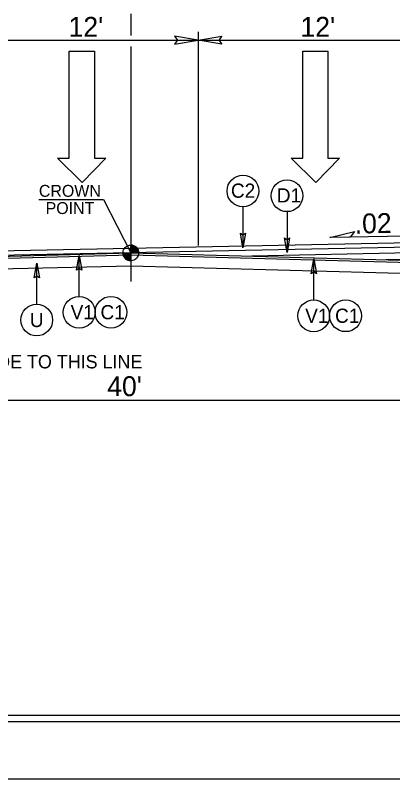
# Model space of a CAD drawing. Extents: x 957297 to 961629, y 830661 to 840840.
# Drawn here: x 959261.2 to 959409.2, y 838515.4 to 838815 of the extents above; entities that cross this region are included whole.
import ezdxf

# ---------------------------------------------------------------- set-up
doc = ezdxf.new("R2010")
doc.units = 0
for name, color, linetype in [('Default', 7, 'Continuous'), ('Old_Level_1', 7, 'Continuous'), ('Old_Level_11', 7, 'Continuous'), ('Prop CMT Pvmt Milling', 7, 'Continuous'), ('Prop Dimension Text', 7, 'Continuous'), ('Prop Lane Arrow CELL', 7, 'Continuous'), ('Sheet Plot Border Inside CELL', 7, 'Continuous'), ('Sheet Plot Border Outside CELL', 7, 'Continuous'), ('Sheet Typical CELL', 7, 'Continuous'), ('Typical ID Circle CELL', 7, 'Continuous'), ('Typical Terminator CELL', 7, 'Continuous'), ('Typical Text Grade Point CELL', 7, 'Continuous'), ('Typical Text ID Circle CELL', 7, 'Continuous')]:
    doc.layers.add(name, color=color, linetype=linetype)

# ---------------------------------------------------------------- blocks, each defined once
blk = doc.blocks.new('Lane Arrow Through')
at = {"layer": 'Prop Lane Arrow CELL'}
for p, q in [((-3.15, 1.6), (-3.15, 3.1)), ((-3.15, 3.1), (0, 0)), ((-17.15, 1.6), (-3.15, 1.6)), ((-17.15, -1.7), (-17.15, 1.6)), ((0, 0), (-3.15, -3.2)), ((-3.15, -1.7), (-17.15, -1.7)), ((-3.15, -3.2), (-3.15, -1.7))]:
    blk.add_line(p, q, dxfattribs=at)

msp = doc.modelspace()

# ---------------------------------------------------------------- linework, layer by layer
at = {"layer": 'Default'}
for p, q in [((959306.49, 838815.61), (959306.49, 838807.02)), ((959306.49, 838802.72), (959306.49, 838710.55))]:
    msp.add_line(p, q, dxfattribs=at)
at = {"layer": 'Old_Level_1'}
for p, q in [((959332.9, 838808.54), (959332.9, 838724.63)), ((959239.42, 838805.18), (959332.9, 838805.18)), ((959332.9, 838805.18), (959426.38, 838805.18)), ((959414.71, 838728.33), (959384.5, 838727.72)), ((959494.54, 838727.27), (959206.42, 838721.44)), ((959494.54, 838725.54), (959206.42, 838719.71)), ((959306.49, 838721.74), (959306.49, 838724.81)), ((959494.54, 838723.29), (959354.01, 838720.44)), ((959303.43, 838721.74), (959306.49, 838721.74)), ((959309.55, 838721.74), (959306.49, 838721.74)), ((959306.49, 838718.69), (959306.49, 838721.74)), ((959306.49, 838721.74), (959306.49, 838718.69)), ((959494.54, 838720.79), (959406.57, 838719.01)), ((959133.56, 838663.97), (959479.39, 838663.97))]:
    msp.add_line(p, q, dxfattribs=at)
for points in [[(959306.52, 838724.81), (959306.52, 838724.81), (959306.52, 838721.74)], [(959306.58, 838724.81), (959306.58, 838721.74)], [(959306.64, 838724.8), (959306.64, 838721.74)], [(959306.71, 838724.79), (959306.71, 838721.74)], [(959306.77, 838724.79), (959306.77, 838721.74)], [(959306.83, 838724.79), (959306.83, 838721.74)], [(959306.89, 838724.78), (959306.89, 838721.74)], [(959306.95, 838724.78), (959306.95, 838721.74)], [(959307, 838724.75), (959307, 838721.74)], [(959307.06, 838724.75), (959307.06, 838721.74)], [(959307.13, 838724.74), (959307.13, 838721.74)], [(959307.19, 838724.72), (959307.19, 838721.74)], [(959307.25, 838724.7), (959307.25, 838721.74)], [(959307.31, 838724.69), (959307.31, 838721.74)], [(959307.38, 838724.67), (959307.38, 838721.74)], [(959307.44, 838724.65), (959307.44, 838721.74)], [(959307.5, 838724.63), (959307.5, 838721.74)], [(959307.56, 838724.61), (959307.56, 838721.74)], [(959307.62, 838724.59), (959307.62, 838721.74)], [(959307.69, 838724.56), (959307.69, 838721.74)], [(959307.75, 838724.54), (959307.75, 838721.74)], [(959307.81, 838724.5), (959307.81, 838721.74)], [(959307.86, 838724.48), (959307.86, 838721.74)], [(959307.92, 838724.46), (959307.92, 838721.74)], [(959307.98, 838724.42), (959307.98, 838721.74)], [(959308.05, 838724.38), (959308.05, 838721.74)], [(959308.11, 838724.34), (959308.11, 838721.74)], [(959308.17, 838724.3), (959308.17, 838721.74)], [(959308.23, 838724.25), (959308.23, 838721.74)], [(959308.29, 838724.22), (959308.29, 838721.74)], [(959308.35, 838724.17), (959308.35, 838721.74)], [(959308.42, 838724.12), (959308.42, 838721.74)], [(959308.48, 838724.08), (959308.48, 838721.74)], [(959308.54, 838724.02), (959308.54, 838721.74)], [(959308.6, 838723.96), (959308.6, 838721.74)], [(959308.67, 838723.9), (959308.67, 838721.74)], [(959308.72, 838723.83), (959308.72, 838721.74)], [(959308.78, 838723.77), (959308.78, 838721.74)], [(959308.84, 838723.71), (959308.84, 838721.74)], [(959308.9, 838723.61), (959308.9, 838721.74)], [(959308.97, 838723.54), (959308.97, 838721.74)], [(959309.03, 838723.45), (959309.03, 838721.74)], [(959309.09, 838723.36), (959309.09, 838721.74)], [(959309.14, 838723.26), (959309.14, 838721.74)], [(959309.21, 838723.15), (959309.21, 838721.74)], [(959309.27, 838723.01), (959309.27, 838721.74)], [(959309.33, 838722.86), (959309.33, 838721.74)], [(959309.39, 838722.7), (959309.39, 838721.74)], [(959309.46, 838722.49), (959309.46, 838721.74)], [(959309.52, 838722.19), (959309.52, 838721.74)], [(959303.45, 838721.74), (959303.45, 838721.42)], [(959303.51, 838721.74), (959303.51, 838721.05)], [(959303.57, 838721.74), (959303.57, 838720.83)], [(959303.63, 838721.74), (959303.63, 838720.65)], [(959303.7, 838721.74), (959303.7, 838720.51)], [(959303.76, 838721.74), (959303.76, 838720.38)], [(959303.81, 838721.74), (959303.81, 838720.27)], [(959303.87, 838721.74), (959303.87, 838720.15)], [(959303.94, 838721.74), (959303.94, 838720.07)], [(959304, 838721.74), (959304, 838719.98)], [(959304.06, 838721.74), (959304.06, 838719.89)], [(959304.12, 838721.74), (959304.12, 838719.82)], [(959304.18, 838721.74), (959304.18, 838719.75)], [(959304.24, 838721.74), (959304.24, 838719.67)], [(959304.3, 838721.74), (959304.3, 838719.6)], [(959304.37, 838721.74), (959304.37, 838719.55)], [(959304.43, 838721.74), (959304.43, 838719.5)], [(959304.49, 838721.74), (959304.49, 838719.44)], [(959304.55, 838721.74), (959304.55, 838719.39)], [(959304.62, 838721.74), (959304.62, 838719.33)], [(959304.67, 838721.74), (959304.67, 838719.29)], [(959304.73, 838721.74), (959304.73, 838719.25)], [(959304.79, 838721.74), (959304.79, 838719.21)], [(959304.85, 838721.74), (959304.85, 838719.16)], [(959304.92, 838721.74), (959304.92, 838719.12)], [(959304.98, 838721.74), (959304.98, 838719.08)], [(959305.04, 838721.74), (959305.04, 838719.05)], [(959305.1, 838721.74), (959305.1, 838719.03)], [(959305.16, 838721.74), (959305.16, 838719)], [(959305.23, 838721.74), (959305.23, 838718.96)], [(959305.29, 838721.74), (959305.29, 838718.94)], [(959305.35, 838721.74), (959305.35, 838718.91)], [(959305.41, 838721.74), (959305.41, 838718.89)], [(959305.47, 838721.74), (959305.47, 838718.87)], [(959305.52, 838721.74), (959305.52, 838718.84)], [(959305.59, 838721.74), (959305.59, 838718.83)], [(959305.65, 838721.74), (959305.65, 838718.81)], [(959305.71, 838721.74), (959305.71, 838718.79)], [(959305.77, 838721.74), (959305.77, 838718.78)], [(959305.83, 838721.74), (959305.83, 838718.76)], [(959305.9, 838721.74), (959305.9, 838718.75)], [(959305.95, 838721.74), (959305.95, 838718.75)], [(959306.02, 838721.74), (959306.02, 838718.73)], [(959306.08, 838721.74), (959306.08, 838718.71)], [(959306.14, 838721.74), (959306.14, 838718.71)], [(959306.21, 838721.74), (959306.21, 838718.71)], [(959306.27, 838721.74), (959306.27, 838718.69)], [(959306.33, 838721.74), (959306.33, 838718.69)], [(959306.38, 838721.74), (959306.38, 838718.69)], [(959306.44, 838721.74), (959306.44, 838718.69), (959306.44, 838718.69)], [(959133.56, 838712.76), (959306.49, 838716.69)], [(959306.49, 838716.69), (959479.42, 838711.98)]]:
    msp.add_lwpolyline(points, dxfattribs=at)
msp.add_circle((959306.49, 838721.75), 3.06, dxfattribs=at)
for start, end in [(359.9905, 89.9905), (179.9905, 269.9905)]:
    msp.add_arc((959306.49, 838721.75), 3.06, start, end, dxfattribs=at)
at = {"layer": 'Old_Level_11'}
for p, q in [((959384.5, 838727.72), (959394.25, 838730.14)), ((959394.25, 838730.14), (959392.52, 838727.88)), ((959392.52, 838727.88), (959384.5, 838727.72))]:
    msp.add_line(p, q, dxfattribs=at)
at = {"layer": 'Prop CMT Pvmt Milling'}
for p, q in [((959219.62, 838719.36), (959306.49, 838721.74)), ((959306.46, 838720.87), (959306.49, 838721.74)), ((959479.4, 838716.16), (959306.46, 838720.87))]:
    msp.add_line(p, q, dxfattribs=at)
for points in [[(959306.49, 838721.74), (959306.46, 838720.87), (959219.62, 838718.49)], [(959306.49, 838721.74), (959479.42, 838717.03)]]:
    msp.add_lwpolyline(points, dxfattribs=at)
at = {"layer": 'Sheet Plot Border Inside CELL'}
msp.add_lwpolyline([(960390.3, 839592.94), (958723.8, 839592.94), (958723.8, 838537.84), (960390.3, 838537.84)], close=True, dxfattribs=at)
at = {"layer": 'Sheet Plot Border Outside CELL'}
msp.add_lwpolyline([(960394.8, 839615.39), (958710.8, 839615.39), (958710.8, 838515.39), (960394.8, 838515.39)], close=True, dxfattribs=at)
at = {"layer": 'Sheet Typical CELL'}
msp.add_lwpolyline([(960377.8, 839590.39), (958877.8, 839590.39), (958877.8, 838540.39), (960377.8, 838540.39)], close=True, dxfattribs=at)
at = {"layer": 'Typical ID Circle CELL'}
for p, q in [((959350.46, 838739.79), (959350.46, 838723.71)), ((959367.74, 838737.93), (959367.74, 838721.84)), ((959286.23, 838704.65), (959286.23, 838720.74)), ((959378.23, 838703.26), (959378.23, 838719.35)), ((959269.59, 838701.59), (959269.59, 838717.68))]:
    msp.add_line(p, q, dxfattribs=at)
for centre in [(959350.46, 838746.02), (959367.74, 838744.15), (959286.23, 838698.43), (959298.7, 838698.45), (959269.59, 838695.37), (959378.22, 838697.04), (959390.7, 838697.06)]:
    msp.add_circle(centre, 6.23, dxfattribs=at)
at = {"layer": 'Typical Terminator CELL'}
for points in [[(959323.67, 838803.59), (959332.9, 838805.18), (959323.62, 838806.82), (959324.8, 838805.18)], [(959342.12, 838803.59), (959332.9, 838805.18), (959342.17, 838806.82), (959340.99, 838805.18)], [(959351.45, 838729.47), (959350.46, 838723.71), (959349.44, 838729.5), (959350.46, 838728.77)], [(959368.73, 838727.61), (959367.74, 838721.84), (959366.72, 838727.64), (959367.74, 838726.9)], [(959285.24, 838714.98), (959286.23, 838720.74), (959287.25, 838714.94), (959286.23, 838715.68)], [(959377.23, 838713.58), (959378.23, 838719.35), (959379.25, 838713.55), (959378.23, 838714.29)], [(959268.6, 838711.92), (959269.59, 838717.68), (959270.62, 838711.89), (959269.59, 838712.62)]]:
    msp.add_lwpolyline(points, close=True, dxfattribs=at)
at = {"layer": 'Typical Text Grade Point CELL'}
for p, q in [((959270.38, 838742.63), (959295.71, 838742.63)), ((959295.71, 838742.63), (959306.49, 838721.74))]:
    msp.add_line(p, q, dxfattribs=at)

# ---------------------------------------------------------------- block references
at = {"layer": 'Old_Level_1', "xscale": 3, "yscale": 3, "rotation": -90.00000000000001}
for p in [(959287.38, 838749.42), (959378.99, 838749.42)]:
    msp.add_blockref('Lane Arrow Through', p, dxfattribs=at)

# ---------------------------------------------------------------- texts
at = {"layer": 'Old_Level_1'}
msp.add_text('GRADE TO THIS LINE', height=5.2473, dxfattribs=at).set_placement((959238.87, 838676.42))
at = {"layer": 'Old_Level_11'}
for s, p in [('CROWN', (959270.44, 838743.75)), ('POINT', (959273.08, 838736.99))]:
    msp.add_text(s, height=4.671, dxfattribs=at).set_placement(p)
at = {"layer": 'Prop Dimension Text'}
for s, rotation, p in [("12'", 0, (959282.07, 838806.56)), ("12'", 0, (959373.02, 838806.56)), ('.02', 1.1839, (959394.36, 838729.3)), ("40'", 0, (959297.22, 838665.53))]:
    msp.add_text(s, height=7.801, rotation=rotation, dxfattribs=at).set_placement(p)
at = {"layer": 'Typical Text ID Circle CELL'}
for s, height, p in [('C2', 5.572, (959345.75, 838743.39)), ('D1', 5.572, (959363.75, 838741.52)), ('V1', 5.572, (959282.89, 838695.69)), ('C1', 5.572, (959294.59, 838695.69)), ('U', 5.57, (959266.89, 838692.63)), ('V1', 5.572, (959374.88, 838694.29)), ('C1', 5.572, (959386.59, 838694.29))]:
    msp.add_text(s, height=height, dxfattribs=at).set_placement(p)

doc.saveas('drawing.dxf')
